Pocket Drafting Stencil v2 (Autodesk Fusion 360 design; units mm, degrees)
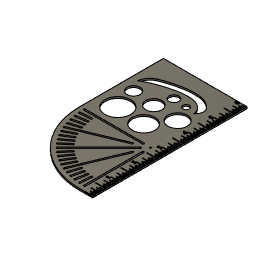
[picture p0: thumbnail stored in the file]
sketch "Sketch1" plane through (0, 0, 0) normal (0, 1, 0) x axis (1, 0, 0)
  line L1 (-76.2, -82.55) -> (-76.2, 0)
  line L2 (6.35, -152.4) -> (-6.35, -152.4)
  line L3 (-71.4375, -81.7562) -> (-13.4937, -81.7562)
  line L4 (-13.4937, -83.3438) -> (-71.4375, -83.3438)
  line L5 (-71.2991, -86.8654) -> (-60.2209, -85.9935)
  line L6 (-60.0963, -87.5761) -> (-71.1746, -88.448)
  line L7 (-70.7603, -91.948) -> (-59.7846, -90.2096)
  line L8 (-59.5363, -91.7775) -> (-70.512, -93.5159)
  line L9 (-69.8244, -96.9726) -> (-59.019, -94.3784)
  line L10 (-58.6484, -95.922) -> (-69.4538, -98.5162)
  line L11 (-68.4972, -101.9082) -> (-57.9286, -98.4743)
  line L12 (-57.438, -99.9841) -> (-68.0066, -103.418)
  line L13 (-66.7868, -106.7246) -> (-19.1204, -86.9805)
  line L14 (-18.5128, -88.4472) -> (-66.1793, -108.1912)
  line L15 (-52.9351, -128.0125) -> (-11.9627, -87.0401)
  line L16 (-10.8401, -88.1627) -> (-51.8125, -129.1351)
  line L17 (-54.8024, -106.3469) -> (-64.7037, -111.3919)
  line L18 (-63.983, -112.8063) -> (-54.0817, -107.7614)
  line L19 (-52.786, -110.0751) -> (-62.2609, -115.8813)
  line L20 (-61.4315, -117.2349) -> (-51.9565, -111.4286)
  line L21 (-58.5403, -121.4496) -> (-49.5501, -114.9179)
  line L22 (-50.4832, -113.6336) -> (-59.4734, -120.1653)
  line L23 (-55.3274, -125.4245) -> (-46.8774, -118.2075)
  line L24 (-47.9084, -117.0004) -> (-56.3584, -124.2174)
  line L25 (-49.2245, -131.5274) -> (-42.0075, -123.0774)
  line L26 (-40.8004, -124.1084) -> (-48.0174, -132.5584)
  line L27 (-45.2496, -134.7403) -> (-38.7179, -125.7501)
  line L28 (-37.4336, -126.6832) -> (-43.9653, -135.6734)
  line L29 (-33.8751, -128.986) -> (-39.6813, -138.4609)
  line L30 (-41.0349, -137.6315) -> (-35.2286, -128.1565)
  line L31 (-30.1469, -131.0024) -> (-35.1919, -140.9037)
  line L32 (-36.6063, -140.183) -> (-31.5614, -130.2817)
  line L33 (-30.5246, -142.9868) -> (-10.7805, -95.3204)
  line L34 (-12.2472, -94.7128) -> (-31.9912, -142.3793)
  line L35 (-25.7082, -144.6972) -> (-22.2743, -134.1286)
  line L36 (-23.7841, -133.638) -> (-27.218, -144.2066)
  line L37 (-20.7726, -146.0244) -> (-18.1784, -135.219)
  line L38 (-19.722, -134.8484) -> (-22.3162, -145.6538)
  line L39 (-15.748, -146.9603) -> (-14.0096, -135.9846)
  line L40 (-15.5775, -135.7363) -> (-17.3159, -146.712)
  line L41 (-10.6654, -147.4991) -> (-9.7935, -136.4209)
  line L42 (-11.3761, -136.2963) -> (-12.248, -147.3746)
  line L43 (-5.5563, -147.6375) -> (-5.5562, -89.6938)
  line L44 (-7.1437, -89.6938) -> (-7.1438, -147.6375)
  line L45 (6.35, 0) -> (6.35, -152.4)
  line L46 (6.35, 0) -> (-76.2, 0)
  curve K1 (-14.0394, -31.9388) -> (-69.85, -31.7289)
  curve K2 (-65.0314, -29.0365) -> (-69.85, -31.7289)
  curve K3 (-64.2258, -28.6756) -> (-65.0314, -29.0365)
  curve K4 (-62.8035, -28.0544) -> (-64.2258, -28.6756)
  curve K5 (-60.9487, -27.2767) -> (-62.8035, -28.0544)
  curve K6 (-59.0846, -26.5247) -> (-60.9487, -27.2767)
  curve K7 (-56.584, -25.5521) -> (-59.0846, -26.5247)
  curve K8 (-54.0588, -24.6367) -> (-56.584, -25.5521)
  curve K9 (-51.5038, -23.8125) -> (-54.0588, -24.6367)
  curve K10 (-49.5727, -23.2435) -> (-51.5038, -23.8125)
  curve K11 (-47.6291, -22.7176) -> (-49.5727, -23.2435)
  curve K12 (-45.6749, -22.2315) -> (-47.6291, -22.7176)
  curve K13 (-43.7124, -21.7785) -> (-45.6749, -22.2315)
  curve K14 (-41.742, -21.3636) -> (-43.7124, -21.7785)
  curve K15 (-39.7614, -21.0034) -> (-41.742, -21.3636)
  curve K16 (-37.7683, -20.7143) -> (-39.7614, -21.0034)
  curve K17 (-35.7646, -20.5018) -> (-37.7683, -20.7143)
  curve K18 (-33.755, -20.3654) -> (-35.7646, -20.5018)
  curve K19 (-31.7438, -20.3034) -> (-33.755, -20.3654)
  curve K20 (-29.7319, -20.336) -> (-31.7438, -20.3034)
  curve K21 (-27.718, -20.4887) -> (-29.7319, -20.336)
  curve K22 (-25.7053, -20.7875) -> (-27.718, -20.4887)
  curve K23 (-23.7384, -21.278) -> (-25.7053, -20.7875)
  curve K24 (-21.86, -22.0064) -> (-23.7384, -21.278)
  curve K25 (-20.1106, -23.0115) -> (-21.86, -22.0064)
  curve K26 (-18.4924, -24.2355) -> (-20.1106, -23.0115)
  curve K27 (-17.0086, -25.6246) -> (-18.4924, -24.2355)
  curve K28 (-15.9535, -26.9364) -> (-17.0086, -25.6246)
  curve K29 (-15.262, -28.091) -> (-15.9535, -26.9364)
  curve K30 (-14.6789, -29.3086) -> (-15.262, -28.091)
  curve K31 (-14.2459, -30.6556) -> (-14.6789, -29.3086)
  curve K32 (-14.0813, -31.6167) -> (-14.2459, -30.6556)
  curve K33 (-14.0394, -31.9388) -> (-14.0813, -31.6167)
  curve K34 (-12.2847, -21.4441) -> (-62.383, -21.0095)
  arc A1 centre (-6.35, -82.55) radius 69.85 clockwise from (-6.35, -152.4) to (-76.2, -82.55)
  circle C1 centre (-6.35, -82.55) radius 0.7937
  arc A2 centre (-71.4375, -82.55) radius 0.7938 clockwise from (-71.4375, -83.3438) to (-71.4375, -81.7562)
  arc A3 centre (-13.4937, -82.55) radius 0.7938 clockwise from (-13.4937, -81.7562) to (-13.4937, -83.3438)
  arc A4 centre (-71.2369, -87.6567) radius 0.7937 clockwise from (-71.1746, -88.448) to (-71.2991, -86.8654)
  arc A5 centre (-60.1586, -86.7848) radius 0.7937 clockwise from (-60.2209, -85.9935) to (-60.0963, -87.5761)
  arc A6 centre (-70.6362, -92.7319) radius 0.7937 clockwise from (-70.512, -93.5159) to (-70.7603, -91.948)
  arc A7 centre (-59.6605, -90.9936) radius 0.7937 clockwise from (-59.7846, -90.2096) to (-59.5363, -91.7775)
  arc A8 centre (-69.6391, -97.7444) radius 0.7938 clockwise from (-69.4538, -98.5162) to (-69.8244, -96.9726)
  arc A9 centre (-58.8337, -95.1502) radius 0.7938 clockwise from (-59.019, -94.3784) to (-58.6484, -95.922)
  arc A10 centre (-68.2519, -102.6631) radius 0.7937 clockwise from (-68.0066, -103.418) to (-68.4972, -101.9082)
  arc A11 centre (-57.6833, -99.2292) radius 0.7937 clockwise from (-57.9286, -98.4743) to (-57.438, -99.9841)
  arc A12 centre (-66.483, -107.4579) radius 0.7937 clockwise from (-66.1793, -108.1912) to (-66.7868, -106.7246)
  arc A13 centre (-18.8166, -87.7138) radius 0.7937 clockwise from (-19.1204, -86.9805) to (-18.5128, -88.4472)
  arc A14 centre (-52.3738, -128.5738) radius 0.7938 clockwise from (-51.8125, -129.1351) to (-52.9351, -128.0125)
  arc A15 centre (-11.4014, -87.6014) radius 0.7938 clockwise from (-11.9627, -87.0401) to (-10.8401, -88.1627)
  arc A16 centre (-54.4421, -107.0541) radius 0.7938 clockwise from (-54.8024, -106.3469) to (-54.0817, -107.7614)
  arc A17 centre (-64.3434, -112.0991) radius 0.7937 clockwise from (-63.983, -112.8063) to (-64.7037, -111.3919)
  arc A18 centre (-52.3713, -110.7519) radius 0.7938 clockwise from (-52.786, -110.0751) to (-51.9565, -111.4286)
  arc A19 centre (-61.8462, -116.5581) radius 0.7937 clockwise from (-61.4315, -117.2349) to (-62.2609, -115.8813)
  arc A20 centre (-59.0069, -120.8075) radius 0.7937 clockwise from (-58.5403, -121.4496) to (-59.4734, -120.1653)
  arc A21 centre (-50.0167, -114.2757) radius 0.7937 clockwise from (-50.4832, -113.6336) to (-49.5501, -114.9179)
  arc A22 centre (-55.8429, -124.8209) radius 0.7937 clockwise from (-55.3274, -125.4245) to (-56.3584, -124.2174)
  arc A23 centre (-47.3929, -117.604) radius 0.7937 clockwise from (-47.9084, -117.0004) to (-46.8774, -118.2075)
  arc A24 centre (-41.404, -123.5929) radius 0.7937 clockwise from (-42.0075, -123.0774) to (-40.8004, -124.1084)
  arc A25 centre (-48.6209, -132.0429) radius 0.7938 clockwise from (-48.0174, -132.5584) to (-49.2245, -131.5274)
  arc A26 centre (-38.0757, -126.2167) radius 0.7937 clockwise from (-38.7179, -125.7501) to (-37.4336, -126.6832)
  arc A27 centre (-44.6075, -135.2069) radius 0.7937 clockwise from (-43.9653, -135.6734) to (-45.2496, -134.7403)
  arc A28 centre (-40.3581, -138.0462) radius 0.7938 clockwise from (-39.6813, -138.4609) to (-41.0349, -137.6315)
  arc A29 centre (-34.5519, -128.5713) radius 0.7937 clockwise from (-35.2286, -128.1565) to (-33.8751, -128.986)
  arc A30 centre (-35.8991, -140.5434) radius 0.7938 clockwise from (-35.1919, -140.9037) to (-36.6063, -140.183)
  arc A31 centre (-30.8541, -130.6421) radius 0.7937 clockwise from (-31.5614, -130.2817) to (-30.1469, -131.0024)
  arc A32 centre (-31.2579, -142.683) radius 0.7937 clockwise from (-30.5246, -142.9868) to (-31.9912, -142.3793)
  arc A33 centre (-11.5138, -95.0166) radius 0.7937 clockwise from (-12.2472, -94.7128) to (-10.7805, -95.3204)
  arc A34 centre (-26.4631, -144.4519) radius 0.7938 clockwise from (-25.7082, -144.6972) to (-27.218, -144.2066)
  arc A35 centre (-23.0292, -133.8833) radius 0.7938 clockwise from (-23.7841, -133.638) to (-22.2743, -134.1286)
  arc A36 centre (-21.5444, -145.8391) radius 0.7938 clockwise from (-20.7726, -146.0244) to (-22.3162, -145.6538)
  arc A37 centre (-18.9502, -135.0337) radius 0.7937 clockwise from (-19.722, -134.8484) to (-18.1784, -135.219)
  arc A38 centre (-16.5319, -146.8362) radius 0.7937 clockwise from (-15.748, -146.9603) to (-17.3159, -146.712)
  arc A39 centre (-14.7936, -135.8605) radius 0.7937 clockwise from (-15.5775, -135.7363) to (-14.0096, -135.9846)
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  vertical L1
  perpendicular L45 L46
  dimension "d74" diameter = 19.05
  dimension "d76" diameter = 15.875
  dimension "d78" diameter = 12.7
  dimension "d80" diameter = 9.525
  dimension "d81" diameter = 6.35
extrude "Extrude1" new body sketch "Sketch1" along normal blind 1.5875
sketch "Sketch2" plane through (0, 1.5875, 0) normal (0, 1, 0) x axis (-1, 0, 0)
  curve K1 (69.85, 31.7289) -> (14.0394, 31.9388)
  curve K2 (12.2847, 21.4441) -> (62.383, 21.0095)
  line L1 (5.5563, 147.6375) -> (5.5562, 89.6938)
  line L2 (7.1437, 89.6938) -> (7.1438, 147.6375)
  line L3 (10.6654, 147.4991) -> (9.7935, 136.4209)
  line L4 (11.3761, 136.2963) -> (12.248, 147.3746)
  line L5 (15.748, 146.9603) -> (14.0096, 135.9846)
  line L6 (15.5775, 135.7363) -> (17.3159, 146.712)
  line L7 (20.7726, 146.0244) -> (18.1784, 135.219)
  line L8 (19.722, 134.8484) -> (22.3162, 145.6538)
  line L9 (25.7082, 144.6972) -> (22.2743, 134.1286)
  line L10 (23.7841, 133.638) -> (27.218, 144.2066)
  line L11 (30.5246, 142.9868) -> (10.7805, 95.3204)
  line L12 (12.2472, 94.7128) -> (31.9912, 142.3793)
  line L13 (31.5614, 130.2817) -> (36.6063, 140.183)
  line L14 (35.1919, 140.9037) -> (30.1469, 131.0024)
  line L15 (35.2286, 128.1565) -> (41.0349, 137.6315)
  line L16 (39.6813, 138.4609) -> (33.8751, 128.986)
  line L17 (43.9653, 135.6734) -> (37.4336, 126.6832)
  line L18 (38.7179, 125.7501) -> (45.2496, 134.7403)
  line L19 (71.4375, 83.3438) -> (13.4937, 83.3438)
  line L20 (13.4938, 81.7562) -> (71.4375, 81.7562)
  line L21 (48.0174, 132.5584) -> (40.8004, 124.1084)
  line L22 (42.0075, 123.0774) -> (49.2245, 131.5274)
  line L23 (55.3274, 125.4245) -> (46.8774, 118.2075)
  line L24 (47.9084, 117.0004) -> (56.3584, 124.2174)
  line L25 (58.5403, 121.4496) -> (49.5501, 114.9179)
  line L26 (50.4832, 113.6336) -> (59.4734, 120.1653)
  line L27 (52.786, 110.0751) -> (62.2609, 115.8813)
  line L28 (61.4315, 117.2349) -> (51.9565, 111.4286)
  line L29 (63.983, 112.8063) -> (54.0817, 107.7614)
  line L30 (54.8024, 106.3469) -> (64.7037, 111.3919)
  line L31 (51.8125, 129.1351) -> (10.8401, 88.1627)
  line L32 (11.9627, 87.0401) -> (52.9351, 128.0125)
  line L33 (66.1793, 108.1912) -> (18.5128, 88.4472)
  line L34 (19.1204, 86.9805) -> (66.7868, 106.7246)
  line L35 (68.0066, 103.418) -> (57.438, 99.9841)
  line L36 (57.9286, 98.4743) -> (68.4972, 101.9082)
  line L37 (69.4538, 98.5162) -> (58.6484, 95.922)
  line L38 (59.019, 94.3784) -> (69.8244, 96.9726)
  line L39 (70.512, 93.5159) -> (59.5363, 91.7775)
  line L40 (59.7846, 90.2096) -> (70.7603, 91.948)
  line L41 (71.1746, 88.448) -> (60.0963, 87.5761)
  line L42 (60.2209, 85.9935) -> (71.2991, 86.8654)
  line L43 (76.2, 82.55) -> (76.2, 0)
  line L44 (3.81, 12.7) -> (-6.35, 12.7)
  line L45 (1.27, 6.35) -> (-6.35, 6.35)
  line L46 (-1.27, 9.525) -> (-6.35, 9.525)
  line L47 (-1.27, 3.175) -> (-6.35, 3.175)
  line L48 (-2.54, 1.5875) -> (-6.35, 1.5875)
  line L49 (-2.54, 4.7625) -> (-6.35, 4.7625)
  line L50 (-2.54, 7.9375) -> (-6.35, 7.9375)
  line L51 (-2.54, 11.1125) -> (-6.35, 11.1125)
  line L52 (-2.54, 20.6375) -> (-6.35, 20.6375)
  line L53 (1.27, 19.05) -> (-6.35, 19.05)
  line L54 (-2.54, 14.2875) -> (-6.35, 14.2875)
  line L55 (-2.54, 23.8125) -> (-6.35, 23.8125)
  line L56 (-2.54, 17.4625) -> (-6.35, 17.4625)
  line L57 (-1.27, 22.225) -> (-6.35, 22.225)
  line L58 (-1.27, 15.875) -> (-6.35, 15.875)
  line L59 (3.81, 25.4) -> (-6.35, 25.4)
  line L60 (-2.54, 39.6875) -> (-6.35, 39.6875)
  line L61 (-2.54, 42.8625) -> (-6.35, 42.8625)
  line L62 (-2.54, 46.0375) -> (-6.35, 46.0375)
  line L63 (1.27, 44.45) -> (-6.35, 44.45)
  line L64 (-2.54, 36.5125) -> (-6.35, 36.5125)
  line L65 (-2.54, 30.1625) -> (-6.35, 30.1625)
  line L66 (-2.54, 33.3375) -> (-6.35, 33.3375)
  line L67 (3.81, 50.8) -> (-6.35, 50.8)
  line L68 (1.27, 31.75) -> (-6.35, 31.75)
  line L69 (-1.27, 47.625) -> (-6.35, 47.625)
  line L70 (-1.27, 41.275) -> (-6.35, 41.275)
  line L71 (-1.27, 34.925) -> (-6.35, 34.925)
  line L72 (-2.54, 49.2125) -> (-6.35, 49.2125)
  line L73 (-1.27, 28.575) -> (-6.35, 28.575)
  line L74 (-2.54, 26.9875) -> (-6.35, 26.9875)
  line L75 (3.81, 38.1) -> (-6.35, 38.1)
  line L76 (-2.54, 58.7375) -> (-6.35, 58.7375)
  line L77 (1.27, 69.85) -> (-6.35, 69.85)
  line L78 (-1.27, 73.025) -> (-6.35, 73.025)
  line L79 (-2.54, 52.3875) -> (-6.35, 52.3875)
  line L80 (-2.54, 55.5625) -> (-6.35, 55.5625)
  line L81 (-2.54, 71.4375) -> (-6.35, 71.4375)
  line L82 (-2.54, 65.0875) -> (-6.35, 65.0875)
  line L83 (-1.27, 66.675) -> (-6.35, 66.675)
  line L84 (-2.54, 74.6125) -> (-6.35, 74.6125)
  line L85 (1.27, 57.15) -> (-6.35, 57.15)
  line L86 (-1.27, 60.325) -> (-6.35, 60.325)
  line L87 (-2.54, 100.0125) -> (-6.35, 100.0125)
  line L88 (-1.27, 92.075) -> (-6.35, 92.075)
  line L89 (-2.54, 96.8375) -> (-6.35, 96.8375)
  line L90 (1.27, 95.25) -> (-6.35, 95.25)
  line L91 (-1.27, 98.425) -> (-6.35, 98.425)
  line L92 (-1.27, 79.375) -> (-6.35, 79.375)
  line L93 (3.81, 88.9) -> (-6.35, 88.9)
  line L94 (-2.54, 80.9625) -> (-6.35, 80.9625)
  line L95 (-2.54, 90.4875) -> (-6.35, 90.4875)
  line L96 (-2.54, 68.2625) -> (-6.35, 68.2625)
  line L97 (3.81, 101.6) -> (-6.35, 101.6)
  line L98 (-1.27, 85.725) -> (-6.35, 85.725)
  line L99 (3.81, 63.5) -> (-6.35, 63.5)
  line L100 (-2.54, 87.3125) -> (-6.35, 87.3125)
  line L101 (-2.54, 84.1375) -> (-6.35, 84.1375)
  line L102 (-2.54, 61.9125) -> (-6.35, 61.9125)
  line L103 (-2.54, 93.6625) -> (-6.35, 93.6625)
  line L104 (-2.54, 77.7875) -> (-6.35, 77.7875)
  line L105 (3.81, 76.2) -> (-6.35, 76.2)
  line L106 (1.27, 82.55) -> (-6.35, 82.55)
  line L107 (-1.27, 53.975) -> (-6.35, 53.975)
  line L108 (-2.54, 150.8125) -> (-6.35, 150.8125)
  line L109 (-2.54, 147.6375) -> (-6.35, 147.6375)
  line L110 (1.27, 133.35) -> (-6.35, 133.35)
  line L111 (-1.27, 136.525) -> (-6.35, 136.525)
  line L112 (-1.27, 149.225) -> (-6.35, 149.225)
  line L113 (-2.54, 134.9375) -> (-6.35, 134.9375)
  line L114 (-2.54, 141.2875) -> (-6.35, 141.2875)
  line L115 (1.27, 146.05) -> (-6.35, 146.05)
  line L116 (3.81, 139.7) -> (-6.35, 139.7)
  line L117 (-2.54, 138.1125) -> (-6.35, 138.1125)
  line L118 (-1.27, 142.875) -> (-6.35, 142.875)
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  parallel L55 L59
  parallel L67 L72
  parallel L84 L105
  parallel L87 L97
extrude "Extrude2" add sketch "Sketch2" along normal blind 0.254
sketch "Sketch3" plane through (0, 1.5875, 0) normal (0, 1, 0) x axis (-1, 0, 0)
  line L1 (1.27, 6.096) -> (-8.89, 6.096)
  line L2 (-8.89, 12.827) -> (3.81, 12.827)
  line L3 (-8.8897, 5.0189) -> (-2.5399, 5.0153)
  line L4 (-8.89, 6.604) -> (1.27, 6.604)
  line L5 (-8.89, 3.429) -> (-1.27, 3.429)
  line L6 (-8.8907, 4.5093) -> (-8.8897, 5.0189)
  line L7 (-2.5401, 4.5079) -> (-8.8907, 4.5093)
  line L8 (3.81, 12.319) -> (-8.89, 12.319)
  line L9 (-1.27, 2.921) -> (-8.89, 2.921)
  line L10 (-8.89, 2.921) -> (-8.89, 3.429)
  line L11 (-8.89, 6.096) -> (-8.89, 6.604)
  line L12 (1.016, 25.146) -> (-8.89, 25.146)
  line L13 (-8.89, 25.654) -> (1.016, 25.654)
  line L14 (-8.89, 25.146) -> (-8.89, 25.654)
  line L15 (-8.89, 12.319) -> (-8.89, 12.827)
  line L16 (-8.89, 1.8415) -> (-2.5403, 1.8379)
  line L17 (-8.891, 1.332) -> (-8.89, 1.8415)
  line L18 (-2.5404, 1.3306) -> (-8.891, 1.332)
  line L19 (-8.891, 7.555) -> (-8.89, 8.0645)
  line L20 (-2.5404, 7.5536) -> (-8.891, 7.555)
  line L21 (-2.5401, 10.7309) -> (-8.8907, 10.7323)
  line L22 (-1.27, 9.144) -> (-8.89, 9.144)
  line L23 (-8.8897, 11.2419) -> (-2.5399, 11.2383)
  line L24 (-8.89, 9.144) -> (-8.89, 9.652)
  line L25 (-8.89, 8.0645) -> (-2.5403, 8.0609)
  line L26 (-8.8907, 10.7323) -> (-8.8897, 11.2419)
  line L27 (-8.89, 9.652) -> (-1.27, 9.652)
  line L28 (-1.27, 21.971) -> (-8.89, 21.971)
  line L29 (-2.5401, 17.3349) -> (-8.8907, 17.3363)
  line L30 (-8.8897, 17.8459) -> (-2.5399, 17.8423)
  line L31 (-8.89, 22.479) -> (-1.27, 22.479)
  line L32 (-2.5404, 14.1576) -> (-8.891, 14.159)
  line L33 (-8.89, 21.971) -> (-8.89, 22.479)
  line L34 (-8.89, 16.256) -> (-1.27, 16.256)
  line L35 (-8.8907, 17.3363) -> (-8.8897, 17.8459)
  line L36 (-8.89, 14.6685) -> (-2.5403, 14.6649)
  line L37 (-8.89, 15.748) -> (-8.89, 16.256)
  line L38 (1.27, 18.923) -> (-8.89, 18.923)
  line L39 (-8.89, 18.923) -> (-8.89, 19.431)
  line L40 (-8.891, 20.382) -> (-8.89, 20.8915)
  line L41 (-8.8907, 23.5593) -> (-8.8897, 24.0689)
  line L42 (-1.27, 15.748) -> (-8.89, 15.748)
  line L43 (-2.5401, 23.5579) -> (-8.8907, 23.5593)
  line L44 (-8.891, 14.159) -> (-8.89, 14.6685)
  line L45 (-8.8897, 24.0689) -> (-2.5399, 24.0653)
  line L46 (-8.89, 19.431) -> (1.27, 19.431)
  line L47 (-2.5404, 20.3806) -> (-8.891, 20.382)
  line L48 (-8.89, 20.8915) -> (-2.5403, 20.8879)
  line L49 (-8.89, 27.2415) -> (-2.5403, 27.2379)
  line L50 (-2.5404, 26.7306) -> (-8.891, 26.732)
  line L51 (-8.89, 28.321) -> (-8.89, 28.829)
  line L52 (-8.89, 35.052) -> (-1.27, 35.052)
  line L53 (-2.5404, 45.7806) -> (-8.891, 45.782)
  line L54 (3.81, 37.719) -> (-8.89, 37.719)
  line L55 (-8.89, 47.371) -> (-8.89, 47.879)
  line L56 (-1.27, 47.371) -> (-8.89, 47.371)
  line L57 (-2.5401, 42.7349) -> (-8.8907, 42.7363)
  line L58 (-8.89, 44.831) -> (1.27, 44.831)
  line L59 (-8.89, 40.0685) -> (-2.5403, 40.0649)
  line L60 (1.27, 44.323) -> (-8.89, 44.323)
  line L61 (-2.5401, 48.9579) -> (-8.8907, 48.9593)
  line L62 (1.016, 50.546) -> (-8.89, 50.546)
  line L63 (-8.89, 38.227) -> (3.81, 38.227)
  line L64 (-8.8897, 36.6419) -> (-2.5399, 36.6383)
  line L65 (-8.89, 46.2915) -> (-2.5403, 46.2879)
  line L66 (-8.89, 32.004) -> (1.27, 32.004)
  line L67 (-8.8907, 36.1323) -> (-8.8897, 36.6419)
  line L68 (-2.5401, 36.1309) -> (-8.8907, 36.1323)
  line L69 (-8.8897, 30.4189) -> (-2.5399, 30.4153)
  line L70 (-8.891, 45.782) -> (-8.89, 46.2915)
  line L71 (-8.89, 37.719) -> (-8.89, 38.227)
  line L72 (-2.5401, 29.9079) -> (-8.8907, 29.9093)
  line L73 (-8.89, 34.544) -> (-8.89, 35.052)
  line L74 (1.27, 31.496) -> (-8.89, 31.496)
  line L75 (-8.891, 26.732) -> (-8.89, 27.2415)
  line L76 (-8.89, 44.323) -> (-8.89, 44.831)
  line L77 (-1.27, 28.321) -> (-8.89, 28.321)
  line L78 (-2.5404, 39.5576) -> (-8.891, 39.559)
  line L79 (-8.89, 28.829) -> (-1.27, 28.829)
  line L80 (-8.8907, 29.9093) -> (-8.8897, 30.4189)
  line L81 (-1.27, 34.544) -> (-8.89, 34.544)
  line L82 (-8.89, 50.546) -> (-8.89, 51.054)
  line L83 (-8.89, 41.656) -> (-1.27, 41.656)
  line L84 (-8.8897, 49.4689) -> (-2.5399, 49.4653)
  line L85 (-8.89, 31.496) -> (-8.89, 32.004)
  line L86 (-8.891, 39.559) -> (-8.89, 40.0685)
  line L87 (-1.27, 41.148) -> (-8.89, 41.148)
  line L88 (-8.8907, 42.7363) -> (-8.8897, 43.2459)
  line L89 (-8.891, 32.955) -> (-8.89, 33.4645)
  line L90 (-8.8907, 48.9593) -> (-8.8897, 49.4689)
  line L91 (-8.89, 51.054) -> (1.016, 51.054)
  line L92 (-8.89, 33.4645) -> (-2.5403, 33.4609)
  line L93 (-2.5404, 32.9536) -> (-8.891, 32.955)
  line L94 (-8.89, 41.148) -> (-8.89, 41.656)
  line L95 (-8.8897, 43.2459) -> (-2.5399, 43.2423)
  line L96 (-8.89, 47.879) -> (-1.27, 47.879)
  line L97 (-2.5401, 80.7079) -> (-8.8907, 80.7093)
  line L98 (-2.5401, 55.3079) -> (-8.8907, 55.3093)
  line L99 (-8.89, 67.056) -> (-1.27, 67.056)
  line L100 (-8.89, 91.948) -> (-8.89, 92.456)
  line L101 (-8.89, 92.456) -> (-1.27, 92.456)
  line L102 (3.81, 63.119) -> (-8.89, 63.119)
  line L103 (-8.891, 77.532) -> (-8.89, 78.0415)
  line L104 (-8.89, 63.627) -> (3.81, 63.627)
  line L105 (-8.891, 71.182) -> (-8.89, 71.6915)
  line L106 (-8.8897, 55.8189) -> (-2.5399, 55.8153)
  line L107 (-8.8907, 68.1363) -> (-8.8897, 68.6459)
  line L108 (-2.5404, 83.7536) -> (-8.891, 83.755)
  line L109 (-2.5401, 74.3579) -> (-8.8907, 74.3593)
  line L110 (-8.89, 66.548) -> (-8.89, 67.056)
  line L111 (-8.89, 65.4685) -> (-2.5403, 65.4649)
  line L112 (-8.8907, 55.3093) -> (-8.8897, 55.8189)
  line L113 (-1.27, 66.548) -> (-8.89, 66.548)
  line L114 (-2.5404, 71.1806) -> (-8.891, 71.182)
  line L115 (-1.27, 91.948) -> (-8.89, 91.948)
  line L116 (-8.89, 85.344) -> (-8.89, 85.852)
  line L117 (-1.27, 85.344) -> (-8.89, 85.344)
  line L118 (-8.89, 85.852) -> (-1.27, 85.852)
  line L119 (-8.89, 69.723) -> (-8.89, 70.231)
  line L120 (-8.8897, 62.0419) -> (-2.5399, 62.0383)
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  parallel L12 L13
  vertical L14
  perpendicular L8 L15
  parallel L62 L91
  vertical L82
  perpendicular L54 L71
  dimension "d121" diameter = 0.508
  dimension "d123" diameter = 0.508
  dimension "d141" diameter = 0.508
  dimension "d142" diameter = 0.508
  dimension "d143" diameter = 0.508
  dimension "d144" diameter = 0.508
  dimension "d145" diameter = 0.508
  dimension "d146" diameter = 0.508
  dimension "d147" diameter = 0.508
  dimension "d148" diameter = 0.508
  dimension "d149" diameter = 0.508
  dimension "d150" diameter = 0.508
  dimension "d151" diameter = 0.508
  dimension "d152" diameter = 0.508
  dimension "d153" diameter = 0.508
  dimension "d154" diameter = 0.508
extrude "Extrude3" cut sketch "Sketch3" against normal blind 0.508 taper -15
extrude "Extrude4" cut sketch "Sketch3" against normal blind 0.508 taper -15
